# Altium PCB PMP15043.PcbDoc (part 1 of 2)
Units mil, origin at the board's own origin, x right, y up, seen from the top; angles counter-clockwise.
Board outline 3400 x 1800 mil, 4 copper layers (Top Layer, Signal Layer 1, Signal Layer 2, Bottom Layer), stack 60.634 mil thick; 118 components, 63 nets, 326 pads, 97 vias.
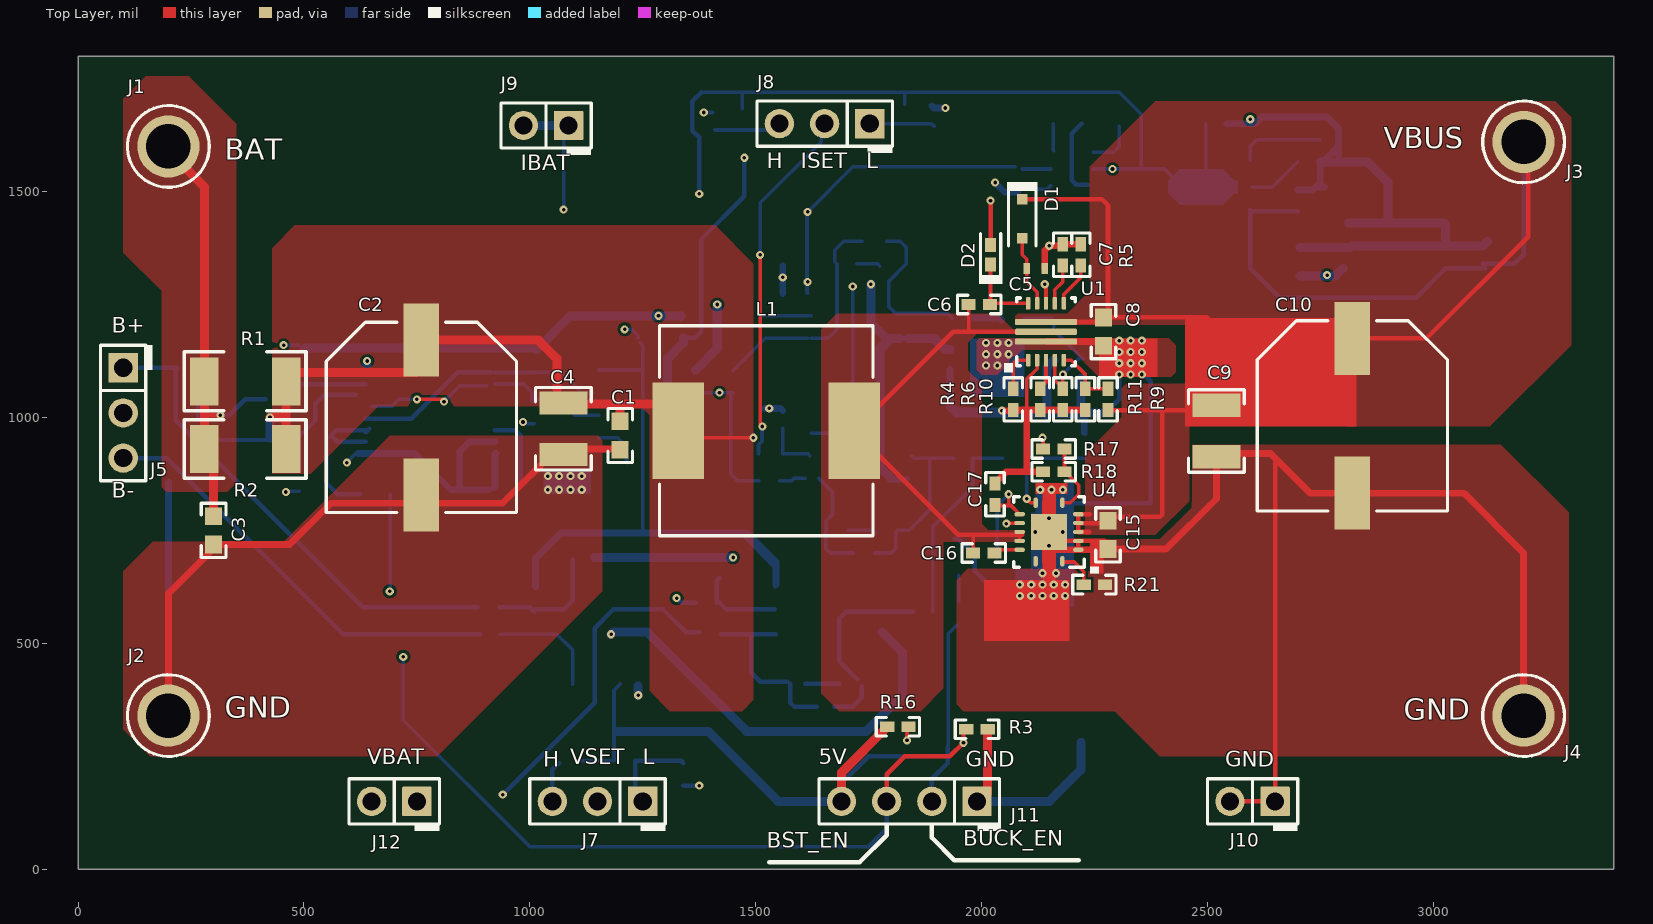
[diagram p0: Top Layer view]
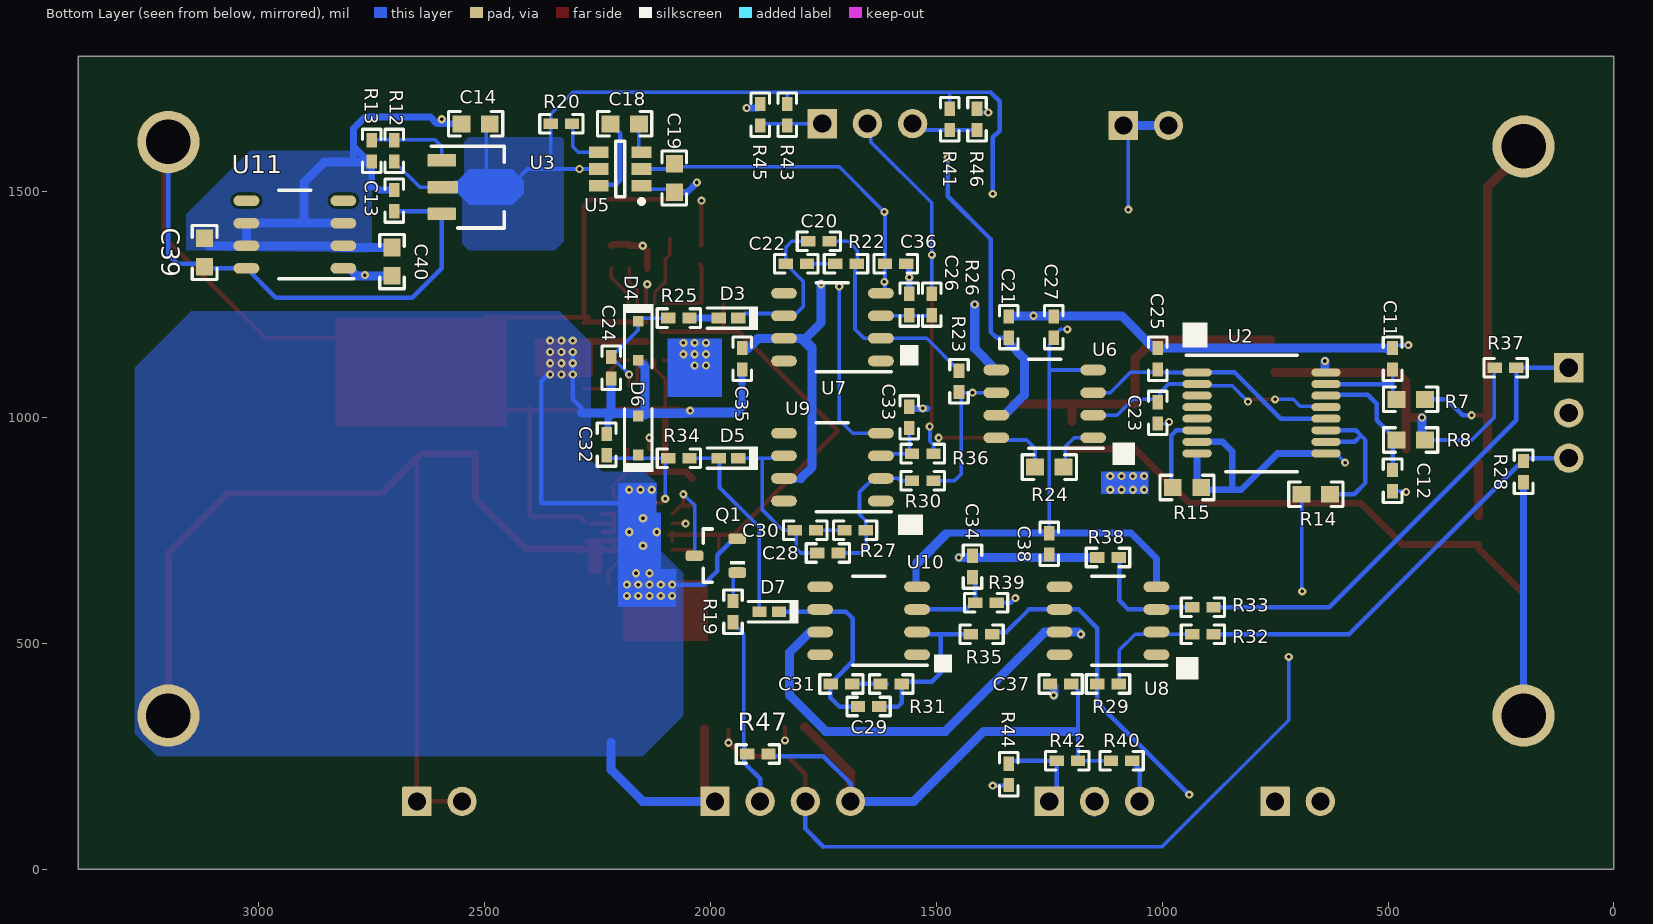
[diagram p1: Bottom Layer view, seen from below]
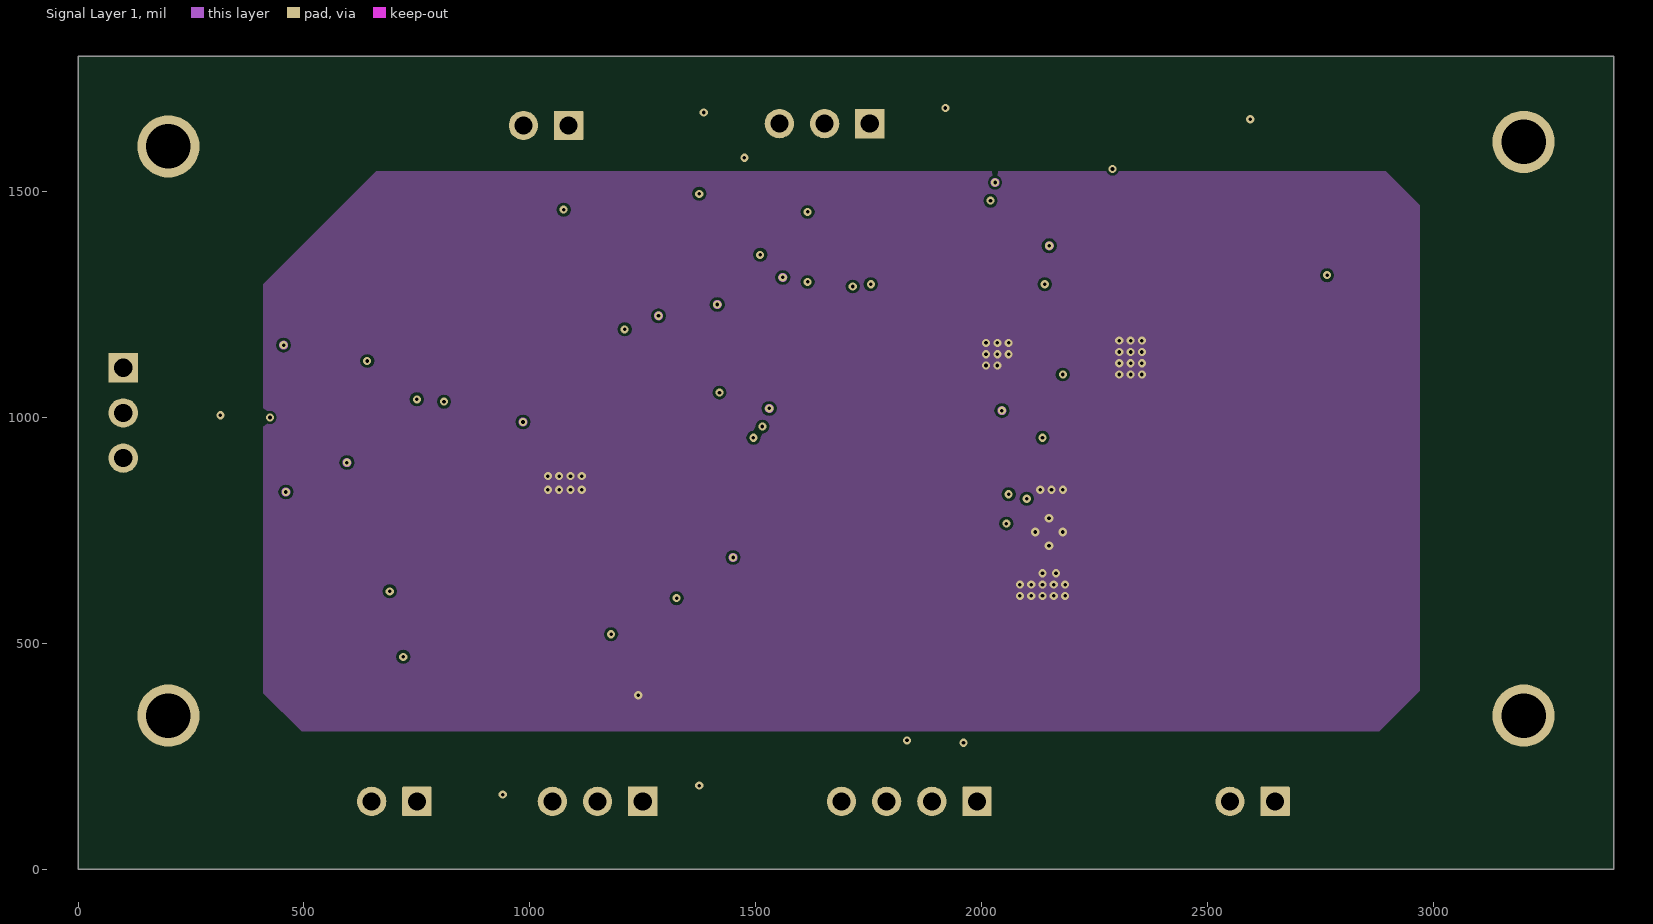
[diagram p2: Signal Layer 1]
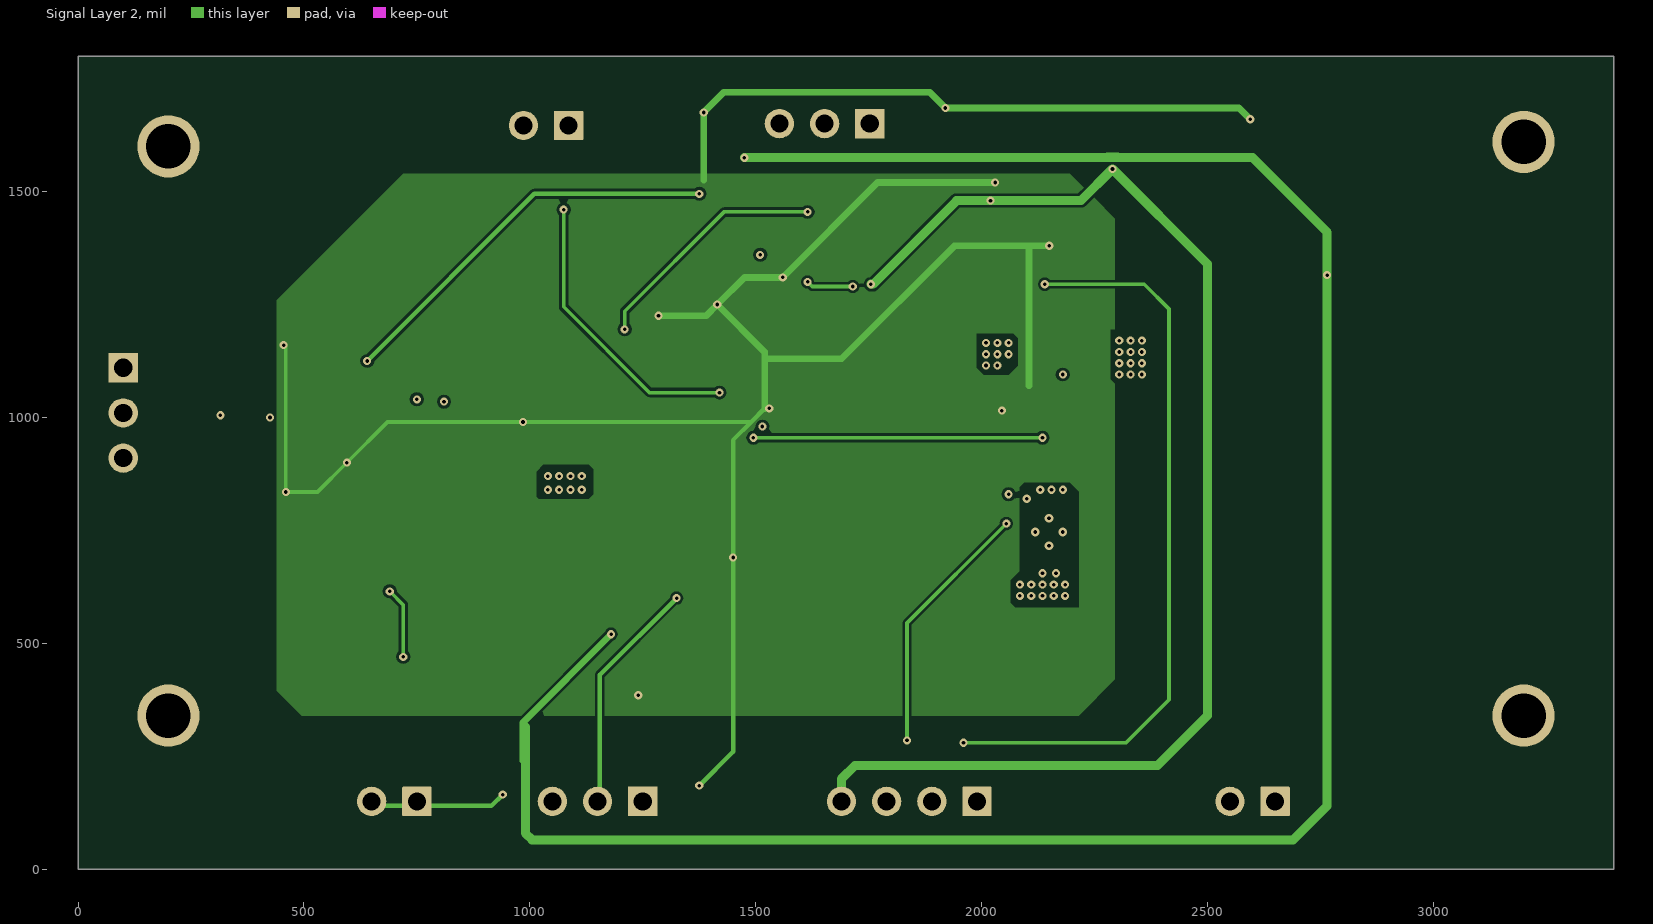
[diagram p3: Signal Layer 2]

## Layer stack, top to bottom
Top Solder: solder mask 0.4, Solder Resist, Dk 3.5
Top Layer: signal copper 1.4
Dielectric 2: prepreg 5, Dk 4.2
Signal Layer 1: signal copper 1.417
Dielectric 3: core 45, FR-4, Dk 4.2
Signal Layer 2: signal copper 1.417
Dielectric1: prepreg 5, Dk 4.2
Bottom Layer: signal copper 1.4
Bottom Solder: solder mask 0.4, Solder Resist, Dk 3.5

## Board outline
0,0 0,1800 3400,1800 3400,0

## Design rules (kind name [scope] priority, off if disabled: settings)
AcuteAngle [All] p1: minimum=4.50000000000000E+0001 checktracksonly=FALSE
AssemblyTestPointUsage [All] p1: valid=2
Clearance [All] p1: gap=6
ComponentClearance ComponentClearance_SHUNT [InComponentClass('Shunt')] p1: gap=0 collisioncheckmode=3 verticalgap=0 showdistances=FALSE
ComponentClearance ComponentClearance_Logo [All] p2: gap=10 collisioncheckmode=3 verticalgap=10 showdistances=FALSE
ComponentClearance ComponentClearance_ScrewToNut [(HasFootprint('NY PMS 440 0025 PH')) vs (HasFootprint('Keystone_1902C'))] p3: gap=5 collisioncheckmode=3 verticalgap=10 showdistances=FALSE
ComponentClearance ComponentClearance_MountingHoles [InComponentClass('Mounting Holes')] p4: gap=250 collisioncheckmode=3 verticalgap=100000 showdistances=FALSE
ComponentClearance ComponentClearance_SmallPassives [HasFootprint('0201*') or HasFootprint('0402*') or HasFootprint('0508') or HasFootprint('0603*') or HasFootprint('0612') or HasFootprint('0805*') or HasFootprint('0815*') or HasFootprint('0830*') or HasFootprint('1206*') or HasFootprint('1210*') or HasFootprint('1808*') or HasFootprint('1812*') or HasFootprint('1825*') or HasFootprint('2010*') or HasFootprint('2220*') or HasFootprint('2225*') or HasFootprint('2512*') or HasFootprint('2728*') or HasFootprint('3518*') vs HasFootprint('0201*') or HasFootprint('0402*') or HasFootprint('0508') or HasFootprint('0603*') or HasFootprint('0612') or HasFootprint('0805*') or HasFootprint('0815*') or HasFootprint('0830*') or HasFootprint('1206*') or HasFootprint('1210*') or HasFootprint('1808*') or HasFootprint('1812*') or HasFootprint('1825*') or HasFootprint('2010*') or HasFootprint('2220*') or HasFootprint('2225*') or HasFootprint('2512*') or HasFootprint('2728*') or HasFootprint('3518*')] p5: gap=20 collisioncheckmode=3 verticalgap=10 showdistances=FALSE
ComponentClearance ComponentClearance_THtoSMT [IsThruComponent vs IsSMTComponent] p6 off: gap=10 collisioncheckmode=3 verticalgap=100000 showdistances=FALSE
ComponentClearance ComponentClearance_THtoTH [IsThruComponent vs IsThruComponent] p7: gap=10.11 collisioncheckmode=3 verticalgap=100000 showdistances=FALSE
ComponentClearance [All] p8: gap=10 collisioncheckmode=3 verticalgap=10 showdistances=FALSE
DiffPairsRouting [All] p1: maxlimit=100 minlimit=10 mostfreqgap=10 toplayer_minwidth=15 toplayer_maxwidth=15 toplayer_prefwidth=15 midlayer1_minwidth=15 midlayer1_maxwidth=15 midlayer1_prefwidth=15 midlayer2_minwidth=15 midlayer2_maxwidth=15 midlayer2_prefwidth=15 bottomlayer_minwidth=15 bottomlayer_maxwidth=15 bottomlayer_prefwidth=15 maxuncoupledlength=1000
FabricationTestPointUsage TestPointUsage [All] p1: valid=2 allowmultiple=FALSE
FabricationTestpoint Testpoint [All] p1: side=3 testpointundercomponent=TRUE minsize=40 maxsize=100 preferedsize=60 minholesize=0 maxholesize=40 preferedholesize=32 testpointgrid=1 allowsidetop=TRUE allowsidebottom=TRUE usegrid=TRUE gridtolerance=0.01
FanoutControl Fanout_LCC [IsLCC] p1: bgadir=Out bgaviamode=Centered fanoutstyle=Auto fanoutdirection=Alternating viagrid=1 // Fanout_LCC (Default Rule)
FanoutControl Fanout_BGA [IsBGA] p2: bgadir=Out bgaviamode=Centered fanoutstyle=Auto fanoutdirection=Alternating viagrid=1 // Fanout_BGA (Default Rule)
FanoutControl Fanout_Default [All] p4: bgadir=Out bgaviamode=Centered fanoutstyle=Auto fanoutdirection=Alternating viagrid=1 // Fanout_Default (Default Rule)
FanoutControl Fanout_Small [(CompPinCount < 5)] p5: bgadir=Out bgaviamode=Centered fanoutstyle=Auto fanoutdirection=OutThenIn viagrid=1 // Fanout_Small (Default Rule)
HoleSize [All] p1: absolutevalues=TRUE maxlimit=200 minlimit=8 maxpercent=80.000 minpercent=20.000
HoleToHoleClearance [All] p1: gap=1 allowstackedmicrovias=TRUE
MinimumAnnularRing MinimumAnnularRing_small [TouchesRoom('BGA_Room')] p1: minimumring=2.8
MinimumAnnularRing [All] p2: minimumring=5
MinimumSolderMaskSliver U2 [InComponent('U1')] p1: minsoldermaskwidth=2
MinimumSolderMaskSliver U1 [InComponent('U2')] p2: minsoldermaskwidth=2
MinimumSolderMaskSliver MinimumSolderMaskSliver_Logo [InComponentClass('Logo') vs InComponentClass('Logo')] p3: minsoldermaskwidth=0.7
MinimumSolderMaskSliver [All] p4: minsoldermaskwidth=2
PlaneClearance [All] p1: clearance=10
PlaneConnect [All] p1: planeconnectstyle=Direct reliefexpansion=10 reliefentries=4 reliefconductorwidth=10 reliefairgap=10
PolygonConnect PolygonConnect-TH-Relief [IsPoly vs (IsThruPin)  And Not (InComponent('U3'))  And Not (InComponent('U4'))] p1: connectstyle=Direct reliefconductorwidth=20 reliefentries=4 polygonreliefangle="90 Angle" airgapwidth=10
PolygonConnect PolygonConnect-DirectConn [All] p2: connectstyle=Direct reliefconductorwidth=10 reliefentries=4 polygonreliefangle="90 Angle" airgapwidth=10
RoutingVias [All] p1: holewidth=10 width=22 viastyle="Through Hole" minholewidth=4 minwidth=10 maxholewidth=200 maxwidth=100
SMDToCorner [All] p1: distance=0
SilkToBoardRegionClearance [Not ((IsComment or IsDesignator) And (Hide <> 'False')) and not InRegion(1000,500,4000,800)] p1:
SilkToSilkClearance [All] p1: silktosilkclearance=3
SilkToSolderMaskClearance "SW PIN" [InNet('SW')] p1: minsilkscreentomaskgap=0 clearancetoexposedcopper=TRUE
SilkToSolderMaskClearance SilkscreenOverComponentPads [IsPad] p2: minsilkscreentomaskgap=0 clearancetoexposedcopper=TRUE
SolderMaskExpansion [All] p1: expansion=1
Width [All] p1: maxlimit=100 minlimit=6 preferedwidth=10 checkconnectedcopper=TRUE
13 further rules are at their usual default settings.

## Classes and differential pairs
component class Header: J5 J7 J8 J9 J10 J11 J12
component class PMP15043-2: C20 C21 C22 C23 C24 C25 C26 C27 C28 C29 C30 C31 C32 C33 C34 C35 C36 C37 C38 D3 D4 D5 D6 D7 J5 J7 J8 J9 J10 J11 J12 R22 R23 R24 R25 R26 R27 R28 R29 R30 R31 R32 R33 R34 R35 R36 R37 R38 R39 R40 R41 R42 R43 R44 R45 R46 U6 U7 U8 U9 U10
component class PMP15043-1: C1 C2 C3 C4 C5 C6 C7 C8 C9 C10 C11 C12 C13 C14 C15 C16 C17 C18 C19 C39 C40 D1 D2 J1 J2 J3 J4 L1 Q1 R1 R2 R3 R4 R5 R6 R7 R8 R9 R10 R11 R12 R13 R14 R15 R16 R17 R18 R19 R20 R21 R47 U1 U2 U3 U4 U5 U11

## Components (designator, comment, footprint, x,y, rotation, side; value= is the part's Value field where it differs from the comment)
C1 "GRM188R61E106MA73D" 0603 1200,960 r270 top
C2 "EEE-FC1E221P" SM_RADIAL_G 760,1000 r270 top
C3 "GRM188R61E106MA73D" 0603 300,750 r270 top
C4 "GRM32ER61A107ME20L" 1210_270 1074.37,974.9 r270 top
C5 "GRM155R61E225KE11D" 0402_070 2120,1330 r180 top
C6 "GRM155R61C104KA88D" 0402 1995,1250 r0 top
C7 "GRM155R61A475MEAAD" 0402 2180,1360 r90 top
C8 "GRM188R61E106MA73D" 0603 2270,1190 r270 top
C9 "GRM32ER61E226KE15L" 1210_270 2520,970 r270 top
C10 "EEE-FC1E221P" SM_RADIAL_G 2820.96,1003.6 r270 top
C11 "GRM155R71A333KA01D" 0402 490,1130 r90 bottom
C12 "GRM155R71A333KA01D" 0402 490,860 r270 bottom
C13 "GRM155R71E104KE14D" 0402 2700,1480 r90 bottom
C14 "GRM188R61A226ME15D" 0603 2520,1650 r0 bottom
C15 "GRM188R61E106MA73D" 0603 2280,740 r270 top
C16 "GRM155R61C104KA88D" 0402 2005,700 r180 top
C17 "GRM155R71H332KA01D" 0402 2030,830 r90 top
C18 "GRM188R61A105KA61D" 0603 2190,1650 r180 bottom
C19 "GRM188R61A226ME15D" 0603 2080,1530 r270 bottom
C20 "GRM1555C1H100JA01D" 0402 1760,1390 r180 bottom
C21 "GRM155R61A105KE15D" 0402 1340,1200 r90 bottom
C22 "GRM155R71C153JA01D" 0402 1810,1340 r180 bottom
C23 "GRM1555C1H100JA01D" 0402 1010,1010 r270 bottom
C24 "GRM1555C1H101JA01D" 0402 2220,1110 r270 bottom
C25 "GRM1555C1H100JA01D" 0402 1010,1130 r90 bottom
C26 "GRM155R70J105KA12D" 0402 1560,1250 r90 bottom
C27 "GRM155R61A105KE15D" 0402 1240,1200 r90 bottom
C28 "GRM1555C1H100JA01D" 0402 1740,700 r180 bottom
C29 "GRM1555C1H100JA01D" 0402 1650,360 r180 bottom
C30 "GRM155R71C153JA01D" 0402 1790,750 r180 bottom
C31 "GRM155R61C104KA88D" 0402 1710,410 r180 bottom
C32 "GRM1555C1H100JA01D" 0402 2230,940 r90 bottom
C33 "GRM155R70J105KA12D" 0402 1560,1000 r90 bottom
C34 "GRM1555C1H100JA01D" 0402 1420,670 r90 bottom
C35 "GRM155R61A105KE15D" 0402 1930,1130 r270 bottom
C36 "GRM155R61A105KE15D" 0402 1590,1340 r180 bottom
C37 "GRM155R61A105KE15D" 0402 1225,410 r0 bottom
C38 "GRM155R61A105KE15D" 0402 1250,720 r270 bottom
C39 "GRM188R61E105KA12D" 0603 3120,1365 r90 bottom
C40 "GRM188R61E106MA73D" 0603 2705,1345 r90 bottom
D1 "BZT52C5V1S-7-F" SOD-323 2090,1440 r270 top
D2 "1N4148X-TP" SOD-523 2020,1360 r90 top
D3 "1N4148X-TP" SOD-523 1960,1220 r0 bottom
D4 "BAT54WS-7-F" SOD-323 2160,1170 r270 bottom
D5 "1N4148X-TP" SOD-523 1960,910 r0 bottom
D6 "BAT54WS-7-F" SOD-323 2160,960 r90 bottom
D7 "1N4148X-TP" SOD-523 1870,570 r0 bottom
J1 "Suggest using a net name here" Keystone1502-2 200,1600 r90 top
J2 "Suggest using a net name here" Keystone1502-2 200,340 r90 top
J3 "Suggest using a net name here" Keystone1502-2 3200,1610 r90 top
J4 "Suggest using a net name here" Keystone1502-2 3200,340 r90 top
J5 "TSW-103-07-G-S" TSW-103-07-G-S 100,1010 r270 top
J7 "TSW-103-07-G-S" TSW-103-07-G-S 1150,150 r180 top
J8 "TSW-103-07-G-S" TSW-103-07-G-S 1652.61,1650.34 r180 top
J9 "TSW-102-07-G-S" TSW-102-07-G-S 1035.91,1646.4 r180 top
J10 "TSW-102-07-G-S" TSW-102-07-G-S 2600,150 r180 top
J11 "TSW-104-07-G-S" TSW-104-07-G-S 1840,150 r180 top
J12 "TSW-102-07-G-S" TSW-102-07-G-S 700,150 r180 top
L1 "7443321000" WE-HCC_1210 1523.3,970.59 r0 top
Q1 "MMBT3904-7-F" SOT-23 1988,694 r0 bottom
R1 "CSRN2010FK10L0" 2010 370,1080 r0 top
R2 "CSRN2010FK10L0" 2010 370,930 r0 top
R3 "CRCW040210K0FKED" 0402 1990,310 r180 top
R4 "CRCW0402845KFKED" 0402 2070,1040 r90 top
R5 "CRCW04021M00FKED" 0402 2220,1360 r90 top
R6 "CRCW040268K1FKED" 0402 2130,1040 r90 top
R7 "CRCW0603499RFKEA" 0603 450,1040 r180 bottom
R8 "CRCW0603499RFKEA" 0603 450,950 r180 bottom
R9 "CRCW04021M00FKED" 0402 2280,1040 r270 top
R10 "CRCW0402511KFKED" 0402 2180,1040 r90 top
R11 "CRCW040280K6FKED" 0402 2230,1040 r90 top
R12 "CRCW04023K74FKED" 0402 2700,1590 r270 bottom
R13 "CRCW040210K0FKED" 0402 2750,1590 r90 bottom
R14 "CRCW06030000Z0EA" 0603 660,830 r180 bottom
R15 "CRCW06030000Z0EA" 0603 945,845 r0 bottom
R16 "CRCW040210K0FKED" 0402 1815,315 r0 top
R17 "CRCW040273K2FKED" 0402 2160,930 r0 top
R18 "CRCW040210K0FKED" 0402 2160,880 r0 top
R19 "CRCW040210K0FKED" 0402 1950,570 r90 bottom
R20 "CRCW040210K0FKED" 0402 2330,1650 r0 bottom
R21 "CRCW0402240KFKED" 0402 2250,630 r180 top
R22 "CRCW04021K00FKED" 0402 1700,1340 r0 bottom
R23 "CRCW040210K0FKED" 0402 1450,1080 r270 bottom
R24 "RC0603FR-07499RL" 0603 1250,890 r180 bottom
R25 "CRCW04024K02FKED" 0402 2070,1220 r180 bottom
R26 "CRCW040210K0FKED" 0402 1510,1250 r90 bottom
R27 "CRCW04021K00FKED" 0402 1680,750 r0 bottom
R28 "CRCW0402100RFKED" 0402 200,880 r270 bottom
R29 "CRCW040251K1FKED" 0402 1120,410 r0 bottom
R30 "CRCW040210K0FKED" 0402 1530,860 r0 bottom
R31 "CRCW04021K00FKED" 0402 1600,410 r0 bottom
R32 "CRCW040251K1FKED" 0402 910,520 r0 bottom
R33 "CRCW040251K1FKED" 0402 910,580 r0 bottom
R34 "CRCW04024K02FKED" 0402 2070,910 r180 bottom
R35 "CRCW040210K0FKED" 0402 1400,520 r0 bottom
R36 "CRCW040210K0FKED" 0402 1530,920 r180 bottom
R37 "CRCW0402100RFKED" 0402 240,1110 r180 bottom
R38 "CRCW040251K1FKED" 0402 1120,690 r180 bottom
R39 "CRCW040210K0FKED" 0402 1390,590 r180 bottom
R40 "CRCW040210K0FKED" 0402 1090,240 r0 bottom
R41 "CRCW040269K8FKED" 0402 1470,1660 r90 bottom
R42 "CRCW040210K0FKED" 0402 1210,240 r180 bottom
R43 "CRCW040290K9FKED" 0402 1830,1670 r90 bottom
R44 "CRCW040242K2FKED" 0402 1340,210 r90 bottom
R45 "CRCW040210K0FKED" 0402 1890,1670 r270 bottom
R46 "CRCW040230K1FKED" 0402 1410,1660 r270 bottom
R47 "CRCW040210K0FKED" 0402 1895,255 r180 bottom
U1 "TPS611781RNWR" RNW0013A 2142.76,1189.64 r90 top
U2 "SN74LV4053ADBR" DB0016A_N 780,1010 r180 bottom
U3 "LM317LIPK" PK0003A_N 2520,1510 r180 bottom
U4 "TPS54821RHLR" RHL0014A 2149.4,746.43 r180 top
U5 "LM2664M6" MF06A_N 2200,1550 r0 bottom
U6 "INA188IDR" D0008A_N 1260,1030 r0 bottom
U7 "OP07CD" D0008A_N 1730,1200 r0 bottom
U8 "OP07CD" D0008A_N 1120,550 r0 bottom
U9 "OP07CD" D0008A_N 1730,890 r0 bottom
U10 "OP07CD" D0008A_N 1650,550 r0 bottom
U11 "UA78L09ACD" D0008A_N 2920,1405 r0 bottom

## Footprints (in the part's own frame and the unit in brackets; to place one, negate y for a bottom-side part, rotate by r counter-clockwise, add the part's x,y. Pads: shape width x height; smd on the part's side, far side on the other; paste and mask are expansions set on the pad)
0402 [mm] "0402 from SM-752 data"
  rect 0.8x0.6 smd: 1(-0.6,0) 2(0.6,0)
  silkscreen extent -1.22,-0.52 1.22,0.52, body extent -0.55,-0.3 0.55,0.3, height 0.6
0402_070 [mil] "SMD, 2-Leads, Body 1.2x0.7mm, Height 0.7mm"
  rect 15x24 smd: 1(-20,0) 2(20,0)
  body extent -24,-14 24,14, height 28
0603 [mm] "0603 from SM-752 data"
  rect 1x0.95 smd: 1(-0.8,0) 2(0.8,0)
  silkscreen extent -1.52,-0.69 1.52,0.69, body extent -0.87,-0.47 0.87,0.47, height 1
1210_270 [mm] "1210"
  rect 1.3x2.7 smd: 1(-1.45,0) 2(1.45,0)
  silkscreen extent -2.32,-1.57 2.32,1.57, body extent -1.7,-1.35 1.7,1.35, height 2.7
2010 [mm] "Chip Capacitor, Body 5.08x2.54mm, IPC Medium Density"
  rect 1.6x2.7 smd: 1(-2.3,0) 2(2.3,0)
  silkscreen extent -3.42,-1.65 3.42,1.65, body extent -2.73,-1.45 2.73,1.45, height 1.66
D0008A_N [mm] "SOIC, 8-Leads, Body 4.9x3.9mm, Pitch 1.27mm, IPC Medium Density"
  oval 1.45x0.6 smd: 1(-2.725,1.905) 2(-2.725,0.635) 3(-2.725,-0.635) 4(-2.725,-1.905) 5(2.725,-1.905) 6(2.725,-0.635) 7(2.725,0.635) 8(2.725,1.905)
  silkscreen extent -3.3,-2.5 0.9,2.5, body extent -3,-2.45 3,2.45, height 1.63
DB0016A_N [mm] "SOP, 16-Leads, Body 6.2x5.3mm, Pitch 0.65mm, IPC Medium Density"
  oval 1.65x0.45 smd: 1(-3.625,2.275) 2(-3.625,1.625) 3(-3.625,0.975) 4(-3.625,0.325) 5(-3.625,-0.325) 6(-3.625,-0.975) 7(-3.625,-1.625) 8(-3.625,-2.275) 9(3.625,-2.275) 10(3.625,-1.625) 11(3.625,-0.975) 12(3.625,-0.325) 13(3.625,0.325) 14(3.625,0.975) 15(3.625,1.625) 16(3.625,2.275)
  silkscreen extent -4.23,-3.3 2,3.25, body extent -3.91,-3.1 3.91,3.1, height 2
Keystone1502-2 [mm] "Double Turret"
  round 3.5 hole 2.5: 1(0,0)
  silkscreen extent -2.3,-2.3 2.3,2.3, body extent -1.6,-1.6 1.59,1.6, height 5.62
MF06A_N [mm] "SOT23, 6-Leads, Body 2.9x1.6mm, Pitch 0.95mm, Lead Span 2.8mm, IPC Medium Density"
  rect 1.1x0.65 smd: 1(-1.2,0.95) 2(-1.2,0) 3(-1.2,-0.95) 4(1.2,-0.95) 5(1.2,0) 6(1.2,0.95)
  silkscreen extent -1.32,-1.55 0.25,1.95, body extent -0.9,-1.55 0.9,1.55, height 1.22
PK0003A_N [mm] "SOT89, 3-Leads, Body 4.5x2.5mm, Pitch 1.5mm, IPC Medium Density"
  rrect14% 1.6x0.7 smd: 1(-1.9,1.5) 3(-1.9,-1.5)
  rrect14% 1.7x0.7 smd: 2(-1.85,0)
  Top Layer region: -1,0.35 -0.35,1 2.05,1 2.7,0.35 2.7,-0.35 2.05,-1 -0.35,-1 -1,-0.35 -1.2,-0.35 -1.2,0.35
  silkscreen extent -2.5,-2.3 1.6,2.3, body extent -2.13,-2.25 1.96,2.25, height 1.6
RHL0014A [mm] "QFN, 14-Leads, Body 3.5x3.5mm, Pitch 0.5mm, Thermal Pad 2.05x2.05mm, TI Recommended"
  oval 0.24x0.6 smd: 1(-0.75,1.65) 7(-0.75,-1.65) 8(0.75,-1.65) 14(0.75,1.65)
  oval 0.6x0.24 smd: 2(-1.65,1) 3(-1.65,0.5) 4(-1.65,0) 5(-1.65,-0.5) 6(-1.65,-1) 9(1.65,-1) 10(1.65,-0.5) 11(1.65,0) 12(1.65,0.5) 13(1.65,1)
  rect 2.05x2.05 smd paste-1.025: 15(0,0)
  Top Layer region: -0.375,-1.025 0.375,-1.025 0.375,-1.75 0.175,-1.75 0.175,-1.425 -0.175,-1.425 -0.175,-1.75 -0.375,-1.75
  Top Layer region: -0.375,1.025 0.375,1.025 0.375,1.75 0.175,1.75 0.175,1.425 -0.175,1.425 -0.175,1.75 -0.375,1.75
  silkscreen extent -1.98,-1.97 1.97,1.97, body extent -1.83,-1.83 1.82,1.82, height 1.01
RNW0013A [mm] "SMD, 13-Leads, Body 3x3.5mm, Pitch 0.5mm"
  rrect40% 0.7x0.25 smd: 1(-1.6,1) 2(-1.6,0.5) 3(-1.6,0) 4(-1.6,-0.5) 5(-1.6,-1) 9(1.6,-1) 10(1.6,-0.5) 11(1.6,0) 12(1.6,0.5) 13(1.6,1)
  rrect40% 0.25x1 on Top Paste: 6(-0.55,1.2) 6(-0.55,0) 6(-0.55,-1.2) 7(0,1.2) 7(0,0) 7(0,-1.2) 8(0.55,1.2) 8(0.55,0) 8(0.55,-1.2)
  rrect57% 0.35x3.5 smd paste-0.5 mask-0.05: 6(-0.55,0) 7(0,0) 8(0.55,0)
  silkscreen extent -1.9,-1.65 1.9,1.65, body extent -1.78,-1.53 1.78,1.53, height 1.01
SM_RADIAL_G [mm] "10 x 10.2mm:  Panasonic G"
  rect 4.1x2 smd: 1(-4.35,0) 2(4.35,0)
  silkscreen extent -5.35,-5.35 5.35,5.35, body extent -5.25,-5.25 5.25,5.25, height 10.5
SOD-323 [mm] "NXP recommended land pattern"
  rect 0.6x0.6 smd paste-0.05: 1(-1.1,0) 2(1.1,0)
  silkscreen extent -2.06,-0.86 1.53,0.86, body extent -1.3,-0.67 1.3,0.68, height 1.1
SOD-523 [mm] "NXP Semiconductor recommended land pattern, nominal STEP model"
  rect 0.8x0.6 smd paste-0.05: 1(-0.55,0) 2(0.55,0)
  silkscreen extent -1.65,-0.66 1.2,0.66, body extent -0.8,-0.4 0.8,0.4, height 0.72
SOT-23 [mm] "SOT23, 3-Leads, Body 2.9x1.3mm, Pitch 0.95mm, Lead Span 2.5mm, IPC Medium Density"
  rrect50% 1x0.6 smd: 1(-1.2,0.95) 2(-1.2,-0.95) 3(1.2,0)
  silkscreen extent -1.62,-1.5 0.7,1.5, body extent -1.16,-1.45 1.21,1.45, height 1
TSW-102-07-G-S [mm] "Samtec 100mil, 1x2, 230 mil above insulator"
  rrect6% 1.65x1.65 hole 1.016: 1(-1.27,0)
  round 1.65 hole 1.016: 2(1.27,0)
  silkscreen extent -2.54,-1.27 2.54,1.65, body extent -2.54,-1.27 2.54,1.27, height 8.38
TSW-103-07-G-S [mm] "Samtec 100mil, 1x3, 230 mil above insulator"
  rect 1.65x1.65 hole 1.016: 1(-2.54,0)
  round 1.65 hole 1.016: 2(0,0) 3(2.54,0)
  silkscreen extent -3.81,-1.27 3.81,1.65, body extent -3.81,-1.27 3.81,1.27, height 8.38
TSW-104-07-G-S [mm] "Samtec 100mil, 1x4, 230 mil above insulator"
  rrect6% 1.65x1.65 hole 1.016: 1(-3.81,0)
  round 1.65 hole 1.016: 2(-1.27,0) 3(1.27,0) 4(3.81,0)
  silkscreen extent -5.16,-1.27 5.08,1.65, body extent -5.08,-1.27 5.08,1.27, height 8.38
WE-HCC_1210 [mm] "WURTH"
  rect 2.9x5.4 smd: 1(-4.95,0) 2(4.95,0)
  silkscreen extent -6,-5.9 6,5.9, body extent -6,-5.85 6,5.85, height 10

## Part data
C1 C3 C8 C15: "CAP, CERM, 10 µF, 25 V, +/- 20%, X5R, 0603"
C2 C10: "CAP, AL, 220 µF, 25 V, +/- 20%, 0.15 ohm, SMD"
C4: "CAP, CERM, 100 µF, 10 V,+/- 20%, X5R, 1210"
C5: "CAP, CERM, 2.2 µF, 25 V,+/- 10%, X5R, 0402"
C6 C16 C31: "CAP, CERM, 0.1 µF, 16 V, +/- 10%, X5R, 0402"
C7: "CAP, CERM, 4.7 µF, 10 V, +/- 20%, X5R, 0402"
C9: "CAP, CERM, 22 µF, 25 V, +/- 10%, X5R, 1210"
C11 C12: "CAP, CERM, 0.033 µF, 10 V,+/- 10%, X7R, 0402"
C13: "CAP, CERM, 0.1 µF, 25 V,+/- 10%, X7R, 0402"
C14 C19: "CAP, CERM, 22 µF, 10 V,+/- 20%, X5R, 0603"
C17: "CAP, CERM, 3300 pF, 50 V,+/- 10%, X7R, 0402"
C18: "CAP, CERM, 1 µF, 10 V,+/- 10%, X5R, 0603"
C20 C23 C25 C28 C29 C32 C34: "CAP, CERM, 10 pF, 50 V,+/- 5%, C0G/NP0, 0402"
C21 C27 C35 C36 C37 C38: "CAP, CERM, 1 µF, 10 V,+/- 10%, X5R, 0402"
C22 C30: "CAP, CERM, 0.015 µF, 16 V,+/- 5%, X7R, 0402"
C24: "CAP, CERM, 100 pF, 50 V,+/- 5%, C0G/NP0, 0402"
C26 C33: "CAP, CERM, 1 µF, 6.3 V,+/- 10%, X7R, 0402"
C39: "CAP, CERM, 1 µF, 25 V,+/- 10%, X5R, 0603"
C40: "CAP, CERM, 10 µF, 25 V,+/- 20%, X5R, 0603"
D1: "Diode, Zener, 5.1 V, 200 mW, SOD-323"
D2 D3 D5 D7: "Diode, Switching, 75 V, 0.3 A, SOD-523"
D4 D6: "Diode, Schottky, 30 V, 0.2 A, SOD-323"
J1 J2 J3 J4: library part 1502-2, "Terminal, Turret, TH, Double"
J5 J7 J8: "Header, 100mil, 3x1, Gold, TH"
J9 J10 J12: "Header, 100mil, 2x1, Gold, TH"
J11: "Header, 100mil, 4x1, Gold, TH"
L1: "Inductor, Shielded Drum Core, Ferrite, 10 µH, 9 A, 0.0144 ohm, SMD"
Q1: library part "MMBT3904-7-F, Diodes Inc.", "Transistor, NPN, 40 V, 0.2 A, SOT-23"
R1 R2: "RES, 0.01, 1%, 1 W, 2010"
R3 R13 R16 R18 R19 R20 R23 R26 R30 R35 R36 R39 R40 R42 R45 R47: "RES, 10.0 k, 1%, 0.063 W, 0402"
R4: "RES, 845 k, 1%, 0.063 W, 0402"
R5 R9: "RES, 1.00 M, 1%, 0.063 W, 0402"
R6: "RES, 68.1 k, 1%, 0.063 W, 0402"
R7 R8 R24: "RES, 499, 1%, 0.1 W, 0603"
R10: "RES, 511 k, 1%, 0.063 W, 0402"
R11: "RES, 80.6 k, 1%, 0.063 W, 0402"
R12: "RES, 3.74 k, 1%, 0.063 W, 0402"
R14 R15: "RES, 0, 5%, 0.1 W, 0603"
R17: "RES, 73.2 k, 1%, 0.063 W, 0402"
R21: "RES, 240 k, 1%, 0.063 W, 0402"
R22 R27 R31: "RES, 1.00 k, 1%, 0.063 W, 0402"
R25 R34: "RES, 4.02 k, 1%, 0.063 W, 0402"
R28 R37: "RES, 100, 1%, 0.063 W, 0402"
R29 R32 R33 R38: "RES, 51.1 k, 1%, 0.063 W, 0402"
R41: "RES, 69.8 k, 1%, 0.063 W, 0402"
R43: "RES, 90.9 k, 1%, 0.063 W, 0402"
R44: "RES, 42.2 k, 1%, 0.063 W, 0402"
R46: "RES, 30.1 k, 1%, 0.063 W, 0402"
U1: "20-V, 10-A Fully-Integrated Synchronous Boost with Load Disconnect, RNW0013A (VQFN-HR-13)"
U2: "Triple 2-Channel Analog Multiplexer/Demultiplexer, DB0016A, LARGE T&R"
U3: "3/8 Pin 100mA Adjustable Positive Regulator, PK0003A (SOT-3)"
U4: "4.5V to 17V Input, 8-A Synchronous Step-Down Converter with Hiccup Current Limit, RHL0014A (VQFN-14)"
U5: "Switched Capacitor Voltage Converter, 6-pin SOT-23"
U6: "36-V, Zero-Drift, Rail-to-Rail-Out Instrumentation Amplifier, D0008A (SOIC-8)"
U7 U8 U9 U10: "Low-Offset Voltage Operational Amplifier, 6 to 36 V, 0 to 70 degC, 8-pin SOIC (D0008A), Green (RoHS & no Sb/Br)"
U11: "Fixed Regulator with 11.5 to 24 V Input and 9 V Output, 0 to 125 degC, 8-Pin SOIC (D), Green (RoHS & no Sb/Br)"

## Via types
v1: diameter 18, hole 8, Top Layer to Bottom Layer, 93 vias
v2: diameter 19.68, hole 8, Top Layer to Bottom Layer, 4 vias

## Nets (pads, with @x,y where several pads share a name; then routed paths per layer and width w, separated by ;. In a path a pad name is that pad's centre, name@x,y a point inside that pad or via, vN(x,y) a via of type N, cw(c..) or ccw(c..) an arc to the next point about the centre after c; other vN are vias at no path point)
+5V: C14.1 C35.1 C37.1 D2.2 J11.4 R12.2 R16.1 R20.2 R40.2 R41.2 R42.2 R43.2 R47.2 U2.16 U3.2 U5.5 U7.7 U9.7 | length 8115.6
  Top Layer w10: D2.2@2020,1381.65 v1(2020,1480)
  Top Layer w20: J11.4@1690,145 J11.4@1690,150 1690,213.62 R16.1@1791.38,315
  Signal Layer 2 w8: v1(1755,1295) 1940,1480 1945,1480
  Signal Layer 2 w10: v1(640,1125) 1010,1495 v1(1375,1495)
  Signal Layer 2 w20: J11.4@1690,150 1690,200 1720,230 2390,230 2500,340 2500,1340 v1(2290,1550) 2220,1480 v1(2020,1480) 1945,1480 1760,1295 v1(1755,1295)
  Bottom Layer w8: R40.2@1113.62,240 R42.2@1185,240 ; R42.2@1186.38,240 1186.38,396.38 C37.1@1200,410 ; 1380,1720 1830,1720 ; R41.2@1470,1683.62 1470,1715 ; 1755,1215 1795,1175 1800,1175 ; 1775,890 1775,885 1795,865 1800,865 U9.7@1837.28,865 1832.28,860 1800,860 ; U7.7@1820,1175 U7.7@1837.28,1175 ; R43.2@1830,1693.62 1830,1720 ; 1885,1175 1906.38,1153.62 1916.38,1153.62 C35.1@1930,1153.62 ; U5.5@2247.24,1550 v1(2290,1550) 2405,1550 2430,1525 ; 2353.62,1551.38 R20.2@2353.62,1650 2353.62,1671.38 2305,1720 1830,1720 ; 2496.38,1526.38 C14.1@2496.38,1650 ; U3.2@2600,1510 2643.62,1510 R12.2@2700,1566.38
  Bottom Layer w10: v1(1375,1495) 1375,1620 1360,1635 1360,1700 1380,1720 ; J11.4@1690,155 1690,190 1750,250 R47.2@1871.38,250
  Bottom Layer w20: U2.16@640,1105 v1(640,1125) ; 1195,305 1395,305 1550,150 J11.4@1690,150 ; v1(1755,1295) 1755,1215 1755,1210 1792.5,1172.5 ; 1795,1175 1792.5,1172.5 ; 1800,865 1775,890 1775,1150 ; U7.7@1820,1175 1800,1175 1795,1170 ; U7.7@1837.28,1175 1885,1175 1895,1175 1916.38,1153.62 1920,1150 C35.1@1930,1150 ; 1775,1150 1795,1170 ; 1775,1150 1775,1155 1792.5,1172.5 ; 1792.5,1172.5 1795,1170
+9V: C21.1 C40.1 U6.7 U8.7 U10.7 U11.1 | length 6743.5
  Signal Layer 2 w15: 985,240 985,325 v1(1180,520)
  Signal Layer 2 w20: 990,315 990,80 1005,65 2690,65 2765,140 v1(2765,1315) 2765,1410 2600,1575 2301.77,1575 2300.77,1576 2279.23,1576 2278.23,1575 v1(1475,1575)
  Bottom Layer w10: C21.1@1340,1176.38 1366.38,1176.38 1380,1190 1380,1395 1475,1490 v1(1475,1575)
  Bottom Layer w20: v1(1180,520) 1185,525 U8.7@1227.28,525 1260,525 1480,305 1745,305 1825,385 1825,480 U10.7@1780,525 ; C21.1@1340,1176.38 1340,1165 1305,1130 1305,1050 U6.7@1350,1005 ; C40.1@2705,1313.5 2783.5,1313.5 U11.1@2800,1330
-5V: C19.1 C27.1 C36.1 C38.1 U5.2 U6.4 U7.4 U8.4 U9.4 U10.4 | length 3711
  Signal Layer 2 w8: v1(1210,1195) 1210,1235 1430,1455 v1@1610,1455 ; v1(1615,1300) 1625,1290 v1(1715,1290)
  Bottom Layer w8: U8.4@1015,625 1015,685 1070,740 C38.1@1250,740 ; U6.4@1152.72,1105 1250,1105 ; v1(1210,1195) 1225,1195 C27.1@1235,1185 ; C27.1@1240,1176.38 C27.1@1240,1180 ; C27.1@1245,1165 1250,1160 1250,1105 ; U10.4@1542.72,625 1542.72,667.28 1470,740 C38.1@1250,740 ; U7.4@1615,1275 1613.62,1276.38 C36.1@1613.62,1340 1613.62,1453.62 v1(1615,1455) 1715,1555 C19.1@2075,1555 ; U9.4@1622.72,965 1685,965 1715,995 v1@1715,1285 ; C19.1@2090,1550 U5.2@2152.76,1550 ; C38.1@1250,740 1250,745 1250,1105
  Bottom Layer w15: U8.4@1012.72,625 1012.72,687.72 1070,745 1250,745 1480,745 1545,680 U10.4@1545,630
B+: J5.1 R33.1 R37.2 | length 1083.4
  Bottom Layer w10: J5.1@95,1105 J5.1@100,1110 R37.2@216.38,1110 ; R37.2@220,1110 R37.2@216.38,1110 ; R33.1@885,580 630,580 216.38,993.62 R37.2@216.38,1110
B-: J5.3 R28.1 R32.1 | length 931.5
  Bottom Layer w10: J5.3@120,910 196.38,910 586.38,520 R32.1@886.38,520 R32.1@890,520
BST_EN: J11.3 R3.2 R14.1 U1.11 | length 3754.2
  Top Layer w8: v1(1960,280) R3.2@1960,310 ; U1.11@2142.76,1252.63 v1@2142.76,1292.24
  Top Layer w10: J11.3@1790,150 1790,210 1830,250 1930,250 v1(1960,280)
  Signal Layer 2 w8: v1(690,615) 720,585 v1(720,470) ; v1(1960,280) 2320,280 2415,375 2415,1240 2360,1295 v1(2140,1295)
  Bottom Layer w8: v1@691.5,616.5 R14.1@691.5,830 ; v1@720,465 720,330 1000,50 1750,50
  Bottom Layer w10: 1750,50 1790,90 J11.3@1790,150
BUCK_EN: J11.2 R19.1 R47.1 | length 432.2
  Bottom Layer w8: R47.1@1926.38,250 1926.38,521.38 R19.1@1945,540
  Bottom Layer w10: J11.2@1890,150 1890,200 1925,235 1925,270
COMP_BOOST: C24.1 D4.1 R10.2 R25.1 U1.4 | length 306.9
  Top Layer w8: U1.4@2162.45,1126.65 2162.45,1082.55 R10.2@2170,1075 ; R10.2@2180,1070 v1(2180,1095)
  Bottom Layer w8: R25.1@2093.62,1220 D4.1@2155,1220 ; D4.1@2160,1215 D4.1@2160,1213.31 2160,1193.62 C24.1@2220,1133.62 ; v1(2180,1095) 2215,1130 C24.1@2225,1130
COMP_BUCK: C32.1 D6.1 R34.1 U4.8 | length 243.4
  Top Layer w8: v1(2100,820) 2108.61,811.39 U4.8@2119.88,811.39
  Bottom Layer w8: v1(2100,820) 2100,910 C32.1@2230,910
FB_BOOST: R9.1 R11.2 U1.5 | length 131.5
  Top Layer w8: U1.5@2182.13,1126.65 2198.35,1126.65 2230,1095 R11.2@2230,1075 ; R11.2@2230,1063.62 2278.62,1063.62 R9.1@2280,1065
GND: C1.2 C2.2 C3.2 C4.2 C5.1 C7.2 C8.2 C9.2 C10.2 C11.2 C12.2 C13.2 C14.2 C15.2 C17.2 C19.2 C21.2 C23.2 C24.2 C25.2 C26.2 C27.2 C32.2 C33.2 C34.2 C35.2 C36.2 C37.2 C38.2 C39.2 C40.2 D4.2 D6.2 J2.1 J4.1 J10.1 J10.2 J11.1 Q1.2 R3.1 R4.1 R5.2 R6.1 R10.1 R11.1 R13.1 R15.1 R18.1 R21.1 R28.2 R38.1 R44.1 R45.1 R46.1 U1.2 U1.6@2142.76,1167.98 U2.7 U2.8 U2.9 U4.2 U4.3 U4.15 U5.1 U6.5 U11.2 U11.3 U11.6 U11.7 | length 17978.1
  Top Layer w8: 2100,1015 2100,1016.38 2100,1085 2123.08,1108.08 U1.2@2123.08,1126.65
  Top Layer w10: U4.15@2180,725 2181.75,726.75 U4.3@2214.37,726.75 ; U4.2@2215,705 2214.37,705.63 U4.2@2214.37,707.06 U4.3@2214.37,726.75 ; C15.2@2275,725 2273.25,726.75 U4.3@2214.37,726.75 ; C15.2@2288.1,703.1 C15.2@2290,705 ; J10.2@2550,150 J10.1@2640,150 ; J10.1@2650,150 2650,900
  Top Layer w15: J2.1@200,340 200,610 C3.2@300,710 ; C3.2@300,718.5 468.5,718.5 560,810 940,810 1060,930 C1.2@1210,930 ; C17.2@2040,865 2055,880 2100,880 ; v1(2045,1015) 2070,1015 2071.38,1016.38 2100,1016.38 R6.1@2130,1016.38 R10.1@2180,1016.38 R11.1@2230,1016.38 ; 2100,1015 2100,880 ; R18.1@2136.38,880 2100,880 ; C5.1@2140,1330 2140,1370 v1(2150,1380) C7.2@2180,1380 ; U1.6@2142.76,1167.98 2272.02,1167.98 C8.2@2280,1160 ; U4.15@2160,710 2162.94,707.06 U4.2@2214.37,707.06 2287.06,707.06 C15.2@2288.5,708.5 ; C7.2@2180,1383.62 2216.38,1383.62 R5.2@2220,1380 ; C15.2@2280,708.5 C15.2@2288.5,708.5 ; C15.2@2290,710 C15.2@2288.5,708.5 ; C9.2@2520,910 2520,820 2408.5,708.5 C15.2@2288.5,708.5 ; C9.2@2520,920 2640,920 2727.66,832.34 C10.2@2820.96,832.34 3067.66,832.34 3200,700 J4.1@3200,340 J4.1@3200,320
  Top Layer w20: J11.1@2013.62,166.38 R3.1@2013.62,310
  Signal Layer 1 w10: v1@460,1160 ccw(c455,1160) v1@460,1160 ; v1@465,835 ccw(c460,835) v1@465,835 ; v1@600,900 ccw(c595,900) v1@600,900 ; v1@990,990 ccw(c985,990) v1@990,990 ; v1@1290,1225 ccw(c1285,1225) v1@1290,1225 ; v1@1420,1250 ccw(c1415,1250) v1@1420,1250 ; v1@1455,690 ccw(c1450,690) v1@1455,690 ; v1@1535,1020 ccw(c1530,1020) v1@1535,1020 ; v1@1565,1310 ccw(c1560,1310) v1@1565,1310 ; v1@2035,1520 ccw(c2030,1520) v1@2035,1520 ; v1@2050,1015 ccw(c2045,1015) v1@2050,1015 ; v1@2155,1380 ccw(c2150,1380) v1@2155,1380
  Signal Layer 2 w8: v1(460,835) v1@460,1160 ; v1@465,835 530,835 v1(595,900) 685,990 v1(985,990) 1490,990
  Signal Layer 2 w10: v1(1375,185) 1450,260 v1(1450,690) 1450,950 1490,990 1520,1020
  Signal Layer 2 w15: v1(1285,1225) 1390,1225 v1(1415,1250) ; 1385,1525 v1(1385,1675) 1430,1720 1885,1720 v1(1920,1685) 2570,1685 v1(2595,1660) ; 1520,1020 1520,1145 v1(1415,1250) ; 1525,1130 1690,1130 1940,1380 2105,1380 ; v1(2030,1520) 1770,1520 v1(1560,1310) 1475,1310 v1(1415,1250) ; 2105,1070 2105,1380 ; v1(2150,1380) 2105,1380
  Bottom Layer w8: v1(455,1160) C11.2@490,1160 ; v1@461.38,836.38 C12.2@490,836.38 ; v1(595,900) 615,920 U2.9@620,920 ; v1@988.62,986.38 C23.2@1010,986.38 ; C25.2@1010,1153.62 1011.38,1153.62 C25.2@1018.62,1153.62 ; C27.2@1240,1225 C27.2@1250,1225 ; v1(1385,1675) R46.1@1405,1675 ; C19.2@2085,1505 2145.16,1505 U5.1@2152.76,1512.6
  Bottom Layer w10: C25.2@1008.62,1153.62 C25.2@1010,1155 ; R44.1@1340,185 v1(1375,185) ; C34.2@1415,690 C34.2@1420,695 ; v1(1415,1250) v1@1415,1255 ; C34.2@1420,693.62 v1@1446.38,693.62 ; Q1.2@1940.76,731.4 1948.6,731.4 1985,695 1985,660 2015,630 v1(2085,630) v1(2110,630) v1(2135,630) 2150,630 ; v1(2045,1015) 2050,1010 2056.69,1003.31 D6.2@2160,1003.31 2216.69,1003.31 ; 2175,810 2375,810 2375,1080 v1@2355,1100 ; C32.2@2225,965 2225,995 2216.69,1003.31 ; C32.2@2230,963.62 2230,1003.31 ; 2230,1010 2230,1003.31 ; 2275,1010 2305,1040 v1(2305,1145) ; 2216.69,1003.31 2230,1003.31
  Bottom Layer w15: J2.1@200,375 R28.2@200,856.38 ; U2.9@620,920 U2.9@650,920 ; U2.9@637.28,920.43 744.57,920.43 825,840 R15.1@910,840 ; 845,845 845,925 866.02,946.02 U2.7@922.72,946.02 ; R15.1@920,845 922.72,847.72 U2.8@922.72,920.43 924.57,920.43 U2.8@925,920 ; C27.2@1240,1223.62 1331.38,1223.62 C21.2@1335,1220 ; 1520,1020 1555,1020 C33.2@1560,1015 ; C26.2@1560,1273.62 v1(1560,1310) C36.2@1560,1335 ; R45.1@1890,1690 1895,1685 v1(1920,1685) ; C35.2@1930,1106.38 1930,1030 1945,1015 v1(2045,1015) ; v1(2030,1520) 2051.5,1498.5 C19.2@2080,1498.5 ; C14.2@2543.62,1650 2605,1650 2620,1665 2765,1665 2790,1640 2790,1600 ; C13.2@2700,1503.62 2733.62,1503.62 2740,1510 ; R13.1@2750,1560 2750,1520 2740,1510 ; R13.1@2755,1565 2790,1600 ; 2760,1510 2740,1510 ; 2790,1580 2790,1600
  Bottom Layer w20: C11.2@500,1150 503.62,1153.62 1008.62,1153.62 C25.2@1010,1153.62 ; C25.2@1011.38,1153.62 1015,1150 1018.62,1153.62 1090,1225 C27.2@1240,1225 ; R38.1@1143.62,690 1415,690 v1(1450,690) ; v1(1240,385) C37.2@1240,405 ; C27.2@1250,1225 v1(1285,1225) C21.2@1335,1225 ; U6.5@1367.28,1105 1415,1152.72 v1(1415,1250) ; 1930,1030 1930,1025 1945,1010 2050,1010 2145,1010 ; J11.1@1990,150 2150,150 2220,220 2220,280 ; 2145,1005 2145,1010 ; D4.2@2160,1126.69 2145,1111.69 2145,1010 ; 2220,1005 2220,1010 ; C24.2@2220,1086.38 2220,1010 ; 2285,1010 2275,1010 2230,1010 2220,1010 ; C40.2@2705,1376.5 2816.5,1376.5 2820,1380 U11.7@3027.28,1380 ; R13.1@2750,1565 2755,1565 2855,1565 2900,1520 2900,1430 ; U11.3@2812.72,1430 2900,1430 ; C39.2@3120,1390 3110,1380 U11.7@3027.28,1380 ; 2145,1010 2220,1010 ; 2900,1430 3025,1430 3027.28,1427.72 U11.7@3027.28,1380
  other v1: 2085,605 2110,605 2135,605 2160,605 2185,605 2160,630 2185,630 2135,655 2165,655 1040,840 1065,840 1090,840 1115,840 2130,840 2155,840 2180,840 1040,870 1065,870 1090,870 1115,870 1530,1020 2305,1095 2330,1095 2355,1095 2010,1115 2035,1115 2305,1120 2330,1120 2355,1120 2010,1140 2035,1140 2060,1140 2330,1145 2355,1145 2010,1165 2035,1165 2060,1165 2305,1170 2330,1170 2355,1170
  other v2: 2149.4,715.92 2118.89,746.43 2179.92,746.43 2149.4,776.94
